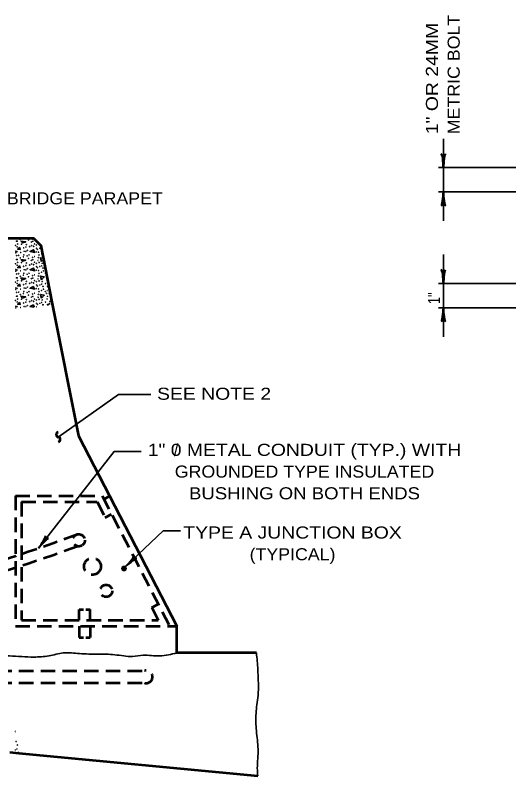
# Model space of a CAD drawing. Extents: x -1 to 679, y 0 to 440.
# Drawn here: x 338.6 to 442.3, y 78.5 to 236 of the extents above; entities that cross this region are included whole.
import ezdxf
from ezdxf.enums import TextEntityAlignment as Align

# ---------------------------------------------------------------- set-up
doc = ezdxf.new("R2010")
doc.units = 0
doc.linetypes.add('MEDIUM_DASHED', pattern=[4.5, 3, -1.5])
doc.layers.add('1', color=7, linetype='Continuous', lineweight=35)

msp = doc.modelspace()

# ---------------------------------------------------------------- hatches: boundary and pattern name
at = {"layer": '1'}
msp.add_hatch(color=256, dxfattribs=at).paths.add_polyline_path([(361.628, 121.46, 1), (360.628, 121.46, 1)])

# ---------------------------------------------------------------- linework, layer by layer
for p, q in [((442.291, 204.463), (426.291, 204.463)), ((442.291, 199.463), (426.291, 199.463)), ((344.442, 185.47), (344.049, 185.049)), ((442.291, 180.463), (426.291, 180.463)), ((342.623, 175.6), (342.309, 176.089)), ((442.291, 175.463), (426.291, 175.463)), ((339.1, 83.277), (339.123, 83.438)), ((339.163, 83.418), (339.318, 83.329))]:
    msp.add_line(p, q, dxfattribs=at)
at = {"layer": '1', "lineweight": 53}
for p, q in [((346.208, 176.58), (351.694, 148.949)), ((351.694, 148.949), (372.07, 109.511)), ((356.965, 135.845), (358.149, 136.457)), ((357.239, 132.047), (358.571, 132.736)), ((366.878, 113.39), (368.211, 114.079)), ((351.87, 110.761), (351.87, 113.011)), ((351.87, 113.011), (352.745, 113.011)), ((353.245, 113.011), (354.12, 113.011)), ((354.12, 110.761), (354.12, 113.011)), ((351.87, 109.511), (351.87, 107.166)), ((354.12, 109.511), (354.12, 107.166)), ((351.87, 107.166), (352.745, 107.166)), ((353.245, 107.166), (354.12, 107.166)), ((337.472, 83.436), (339.326, 83.26)), ((339.326, 83.26), (388.821, 78.547))]:
    msp.add_line(p, q, dxfattribs=at)
at = {"layer": '1', "linetype": 'MEDIUM_DASHED', "lineweight": 53}
for p, q in [((338.62, 136.511), (338.62, 109.511)), ((338.62, 136.511), (356.62, 136.511)), ((356.62, 136.511), (370.57, 109.511)), ((339.87, 135.261), (339.87, 110.761)), ((339.87, 135.261), (355.578, 135.261)), ((355.578, 135.261), (357.239, 132.047)), ((366.878, 113.39), (368.236, 110.761)), ((339.87, 110.761), (368.236, 110.761)), ((338.62, 109.511), (372.07, 109.511)), ((312.37, 100.273), (365.37, 100.273)), ((312.37, 97.784), (365.37, 97.784))]:
    msp.add_line(p, q, dxfattribs=at)
at = {"layer": '1'}
for points in [[(427.291, 210.463), (427.291, 204.463), (427.291, 199.463), (427.291, 193.463)], [(339.449, 187.989), (339.069, 187.589), (339.649, 187.549), (339.449, 187.949)], [(342.349, 187.469), (341.689, 187.109), (342.669, 186.929), (342.309, 187.489)], [(427.291, 186.463), (427.291, 180.463), (427.291, 175.463), (427.291, 169.463)], [(344.069, 185.009), (343.829, 185.809), (344.398, 185.692)], [(339.449, 184.189), (339.069, 183.789), (339.649, 183.749), (339.449, 184.149)], [(342.349, 183.669), (341.689, 183.309), (342.669, 183.129), (342.309, 183.689)], [(344.069, 181.209), (343.829, 182.009), (344.609, 181.849), (344.049, 181.249)], [(339.449, 180.389), (339.069, 179.989), (339.649, 179.949), (339.449, 180.349)], [(342.349, 179.869), (341.689, 179.509), (342.669, 179.329), (342.309, 179.889)], [(345.53, 179.991), (345.229, 179.869), (345.562, 179.831)], [(344.069, 177.409), (343.829, 178.209), (344.609, 178.049), (344.049, 177.449)], [(339.449, 176.589), (339.069, 176.189), (339.649, 176.149), (339.449, 176.549)], [(342.349, 176.069), (341.689, 175.709), (342.402, 175.578)], [(345.859, 176.324), (345.229, 176.069), (345.473, 176.041)], [(347.513, 148.689), (359.957, 157.502), (366.674, 157.502)], [(343.411, 125.676), (359.062, 145.677), (364.704, 145.677)], [(361.424, 121.863), (369.272, 129.282), (372.854, 129.282)]]:
    msp.add_lwpolyline(points, dxfattribs=at)
at = {"layer": '1', "lineweight": 53}
for points in [[(333.37, 189.85), (342.37, 189.85), (343.87, 188.35), (346.208, 176.58)], [(388.57, 104.011), (372.07, 104.011), (372.07, 109.511)]]:
    msp.add_lwpolyline(points, dxfattribs=at)
at = {"layer": '1'}
for points in [[(339.729, 189.229), (340.769, 189.109), (340.089, 188.869)], [(339.729, 185.429), (340.769, 185.309), (340.089, 185.069)], [(339.729, 181.629), (340.769, 181.509), (340.089, 181.269)], [(339.729, 177.829), (340.769, 177.709), (340.089, 177.469)]]:
    msp.add_lwpolyline(points, close=True, dxfattribs=at)
for centre in [(338.875, 189.233), (339.101, 189.248), (339.644, 189.579), (340.32, 189.805), (341.341, 189.473), (341.937, 189.062), (342.215, 189.699), (342.255, 189.208), (338.643, 188.373), (339.008, 188.06), (339.101, 188.651), (339.909, 188.612), (340.347, 187.848), (340.797, 188.02), (340.903, 188.532), (341.606, 188.113), (342.003, 188.307), (342.401, 188.179), (342.6, 188.665), (342.957, 188.466), (343.024, 187.781), (343.183, 187.569), (343.541, 188.612), (343.7, 187.781), (338.722, 187.158), (338.735, 186.84), (338.894, 186.243), (338.955, 187.079), (339.313, 186.296), (339.737, 186.906), (340.32, 186.005), (340.373, 186.403), (340.453, 187.132), (340.797, 187.092), (341.062, 186.19), (341.115, 187.331), (341.46, 186.403), (342.215, 185.899), (342.626, 186.071), (343.024, 187.039), (343.395, 185.832), (343.408, 186.946), (343.527, 186.376), (344.071, 186.615), (338.643, 184.573), (338.875, 185.433), (339.008, 184.26), (339.101, 185.448), (339.101, 184.851), (339.644, 185.779), (339.909, 184.812), (340.903, 184.732), (341.341, 185.673), (341.606, 184.313), (341.937, 185.262), (342.003, 184.507), (342.255, 185.408), (342.401, 184.379), (342.6, 184.865), (342.957, 184.666), (343.355, 185.236), (343.541, 184.812), (344.19, 184.666), (338.722, 183.358), (338.735, 183.04), (338.955, 183.279), (339.737, 183.106), (340.347, 184.048), (340.453, 183.332), (340.797, 184.22), (340.797, 183.292), (341.115, 183.531), (343.024, 183.981), (343.024, 183.239), (343.183, 183.769), (343.408, 183.146), (343.7, 183.981), (344.071, 182.815), (344.097, 184.14), (344.323, 183.676), (344.376, 183.676), (344.442, 183.093), (338.875, 181.633), (338.894, 182.443), (339.101, 181.648), (339.313, 182.496), (339.644, 181.979), (340.32, 182.205), (340.373, 182.603), (341.062, 182.39), (341.341, 181.873), (341.46, 182.603), (341.937, 181.462), (342.215, 182.099), (342.255, 181.608), (342.626, 182.271), (343.355, 181.436), (343.395, 182.032), (343.527, 182.576), (344.839, 182.603), (345.21, 181.078), (338.643, 180.773), (338.722, 179.558), (339.008, 180.46), (339.101, 181.051), (339.909, 181.012), (340.347, 180.248), (340.453, 179.532), (340.797, 180.42), (340.903, 180.932), (341.115, 179.731), (341.606, 180.513), (342.003, 180.707), (342.401, 180.579), (342.6, 181.065), (342.957, 180.866), (343.024, 180.181), (343.183, 179.969), (343.541, 181.012), (343.7, 180.181), (344.097, 180.34), (344.19, 180.866), (344.323, 179.876), (344.376, 179.876), (344.879, 180.446), (338.735, 179.24), (338.894, 178.643), (338.955, 179.479), (339.313, 178.696), (339.644, 178.179), (339.737, 179.306), (340.32, 178.405), (340.373, 178.803), (340.797, 179.492), (341.062, 178.59), (341.341, 178.073), (341.46, 178.803), (342.215, 178.299), (342.626, 178.471), (343.024, 179.439), (343.395, 178.232), (343.408, 179.346), (343.527, 178.776), (344.071, 179.015), (344.442, 179.293), (344.839, 178.803), (345.118, 178.431), (345.25, 179.028), (345.635, 178.405), (338.643, 176.973), (338.875, 177.833), (339.008, 176.66), (339.101, 177.848), (339.101, 177.251), (339.909, 177.212), (340.347, 176.448), (340.797, 176.62), (340.903, 177.132), (341.606, 176.713), (341.937, 177.662), (342.003, 176.907), (342.255, 177.808), (342.401, 176.779), (342.6, 177.265), (342.957, 177.066), (343.024, 176.381), (343.355, 177.636), (343.541, 177.212), (343.7, 176.381), (344.097, 176.54), (344.19, 177.066), (344.879, 176.646), (345.21, 177.278), (345.277, 177.822), (345.767, 176.739), (345.979, 177.053), (338.722, 175.758), (338.735, 175.44), (338.955, 175.679), (339.737, 175.506), (340.453, 175.732), (340.797, 175.692), (341.115, 175.931), (343.183, 176.169), (344.323, 176.076), (344.376, 176.076), (338.649, 87.716), (338.795, 85.634), (338.649, 83.916), (338.928, 84.088), (339.047, 84.937)]:
    msp.add_circle(centre, 0.0265, dxfattribs=at)
at = {"layer": '1', "linetype": 'MEDIUM_DASHED', "lineweight": 53}
for centre, radius in [((351.755, 127.308), 1.261), ((354.595, 121.906), 1.75), ((357.427, 116.827), 1.261)]:
    msp.add_circle(centre, radius, dxfattribs=at)
at = {"layer": '1', "lineweight": 13}
msp.add_circle((361.128, 121.46), 0.5, dxfattribs=at)
at = {"layer": '1'}
msp.add_arc((343.024, 175.639), 0.0265, 30.26479, 165.70427, dxfattribs=at)
at = {"layer": '1', "lineweight": 53}
for centre, start, end in [((347.6, 149.195), 105.71531, 260.28469), ((347.427, 148.184), 285.71531, 80.28469)]:
    msp.add_arc(centre, 0.513, start, end, dxfattribs=at)
at = {"layer": '1', "linetype": 'MEDIUM_DASHED', "lineweight": 53}
for centre, radius, start, end in [((237.574, 434.084), 326.063, 282.8105, 290.45715), ((227.003, 466.974), 362.924, 283.19898, 290.06715), ((365.747, 99.029), 1.3, 253.19227, 106.80773)]:
    msp.add_arc(centre, radius, start, end, dxfattribs=at)
at = {"layer": '1', "lineweight": 40}
for centre, major_axis, ratio, start_param, end_param in [((427.015, 205.555), (0.156, -1.786), 0.122415, 0.8963533, 3.1415927), ((427.015, 205.555), (0.156, -1.786), 0.122415, 0.8963533, 3.1415927), ((427.503, 205.584), (-0.176, -1.756), 0.07063, 3.1407148, 5.41811), ((427.503, 205.584), (-0.176, -1.756), 0.07063, 3.1407148, 5.41811), ((427.079, 198.343), (0.176, 1.756), 0.07063, 3.1407148, 5.41811), ((427.079, 198.343), (0.176, 1.756), 0.07063, 3.1407148, 5.41811), ((427.567, 198.372), (-0.156, 1.786), 0.122415, 0.8963533, 3.1415927), ((427.567, 198.372), (-0.156, 1.786), 0.122415, 0.8963533, 3.1415927), ((427.015, 181.555), (0.156, -1.786), 0.122415, 0.8963533, 3.1415927), ((427.015, 181.555), (0.156, -1.786), 0.122415, 0.8963533, 3.1415927), ((427.503, 181.584), (-0.176, -1.756), 0.07063, 3.1407148, 5.41811), ((427.503, 181.584), (-0.176, -1.756), 0.07063, 3.1407148, 5.41811), ((427.079, 174.343), (0.176, 1.756), 0.07063, 3.1407148, 5.41811), ((427.079, 174.343), (0.176, 1.756), 0.07063, 3.1407148, 5.41811), ((427.567, 174.372), (-0.156, 1.786), 0.122415, 0.8963533, 3.1415927), ((427.567, 174.372), (-0.156, 1.786), 0.122415, 0.8963533, 3.1415927), ((343.866, 126.706), (-0.978, -1.503), 0.122415, 0.8963533, 3.1415927), ((344.268, 126.428), (1.221, 1.275), 0.07063, 6.2823074, 8.5597026), ((362.027, 122.813), (-1.19, -1.34), 0.122415, 0.8963533, 3.1415927), ((362.384, 122.479), (-1.397, -1.079), 0.07063, 3.1407148, 5.41811)]:
    msp.add_ellipse(centre, major_axis=major_axis, ratio=ratio, start_param=start_param, end_param=end_param, dxfattribs=at)
at = {"layer": '1'}
for points in [[(317.87, 104.1), (320.537, 104.092), (323.89, 103.613), (328.081, 103.374), (330.954, 103.613), (334.546, 103.493), (337.42, 103.374), (342.449, 103.134), (345.562, 103.374), (348.556, 103.972), (351.908, 103.853), (355.74, 103.733), (359.212, 103.613), (362.924, 103.254), (365.08, 103.493), (368.552, 103.374), (372.07, 104.011)], [(388.57, 104.011), (388.85, 100.531), (388.952, 98.195), (388.901, 95.149), (388.647, 93.27), (388.444, 89.716), (388.546, 87.837), (388.901, 84.079), (388.85, 82.099), (388.749, 80.119), (388.821, 78.547)]]:
    msp.add_spline(points, degree=3, dxfattribs=at)

# ---------------------------------------------------------------- texts
for s, width, p in [('METRIC BOLT', 1.1, (430.672, 211.389)), ('1" OR 24MM', 1.2, (426.172, 211.389)), ('1"', 0.8, (426.577, 176.214))]:
    msp.add_text(s, height=2.5, rotation=90, dxfattribs=dict(at, width=width)).set_placement(p)
for s, width, p in [('BRIDGE PARAPET', 1.1, (336.878, 196.867)), ('SEE NOTE 2', 1.2, (367.974, 156.401))]:
    msp.add_text(s, height=2.5, dxfattribs=dict(at, width=width)).set_placement(p)
for s, width, p in [('1" 0 METAL CONDUIT (TYP.) WITH', 1.2, (398.52, 144.786)), ('GROUNDED TYPE INSULATED', 1.1, (398.52, 140.286)), ('BUSHING ON BOTH ENDS', 1.15, (398.52, 135.786)), ('TYPE A JUNCTION BOX', 1.2, (396.044, 127.671)), ('(TYPICAL)', 1.1, (396.044, 123.171))]:
    msp.add_text(s, height=2.5, dxfattribs=dict(at, width=width)).set_placement(p, align=Align.CENTER)
msp.add_text('/', height=2.5, dxfattribs=at).set_placement((371.454, 144.745))

doc.saveas('drawing.dxf')
